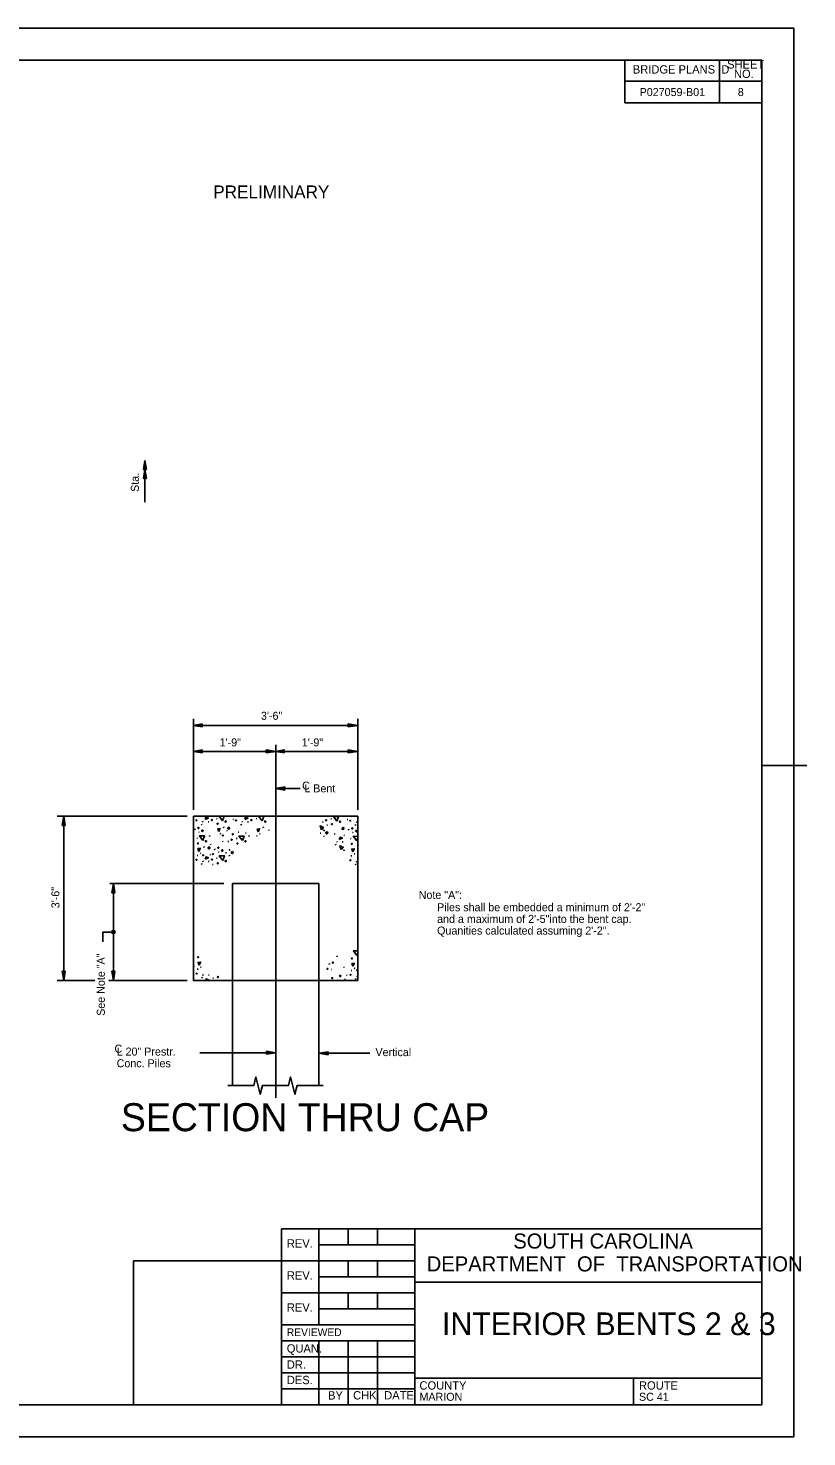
# Model space of a CAD drawing. Extents: x 437 to 537, y 571 to 720.
# Drawn here: x 503.3 to 536.8, y 570.8 to 631.3 of the extents above; entities that cross this region are included whole.
import ezdxf

# ---------------------------------------------------------------- set-up
doc = ezdxf.new("R2010")
doc.units = 0
for name, color, linetype in [('BR_AUTO DIMENSION', 7, 'Continuous'), ('BR_BORDER LINES', 7, 'Continuous'), ('BR_CENTER LINES', 7, 'Continuous'), ('BR_CONCRETE', 7, 'Continuous'), ('BR_PRESTRESSED BEAM', 7, 'Continuous'), ('BR_TABLE LINES', 7, 'Continuous'), ('BR_TEXT', 7, 'Continuous'), ('Default', 7, 'Continuous'), ('RD_SHT_IplotShp', 7, 'Continuous')]:
    doc.layers.add(name, color=color, linetype=linetype)

msp = doc.modelspace()

# ---------------------------------------------------------------- linework, layer by layer
at = {"layer": 'BR_AUTO DIMENSION'}
for p, q in [((508.265, 612.313), (508.329, 612.699)), ((508.394, 612.313), (508.265, 612.313)), ((508.265, 611.926), (508.329, 612.313)), ((508.329, 610.909), (508.329, 612.699)), ((508.329, 612.699), (508.394, 612.313)), ((508.329, 612.313), (508.394, 611.926)), ((508.394, 611.926), (508.265, 611.926)), ((517.472, 601.322), (517.059, 601.39)), ((517.059, 601.39), (517.059, 601.253)), ((517.059, 601.253), (517.472, 601.322)), ((513.943, 600.207), (513.53, 600.276)), ((513.53, 600.276), (513.53, 600.138)), ((513.53, 600.138), (513.943, 600.207)), ((517.472, 600.207), (517.059, 600.276)), ((517.059, 600.276), (517.059, 600.138)), ((517.059, 600.138), (517.472, 600.207)), ((513.943, 598.61), (514.341, 598.677)), ((514.342, 598.544), (513.943, 598.61)), ((514.341, 598.677), (514.342, 598.544)), ((504.775, 597.022), (504.842, 597.421)), ((504.842, 597.421), (504.908, 597.022)), ((504.908, 597.022), (504.775, 597.022)), ((506.906, 594.129), (506.973, 594.528)), ((507.039, 594.129), (506.906, 594.129)), ((506.973, 594.528), (507.039, 594.129)), ((506.995, 592.445), (506.52, 592.445)), ((506.52, 592.445), (506.52, 592.019)), ((504.908, 590.761), (504.775, 590.762)), ((504.775, 590.762), (504.842, 590.363)), ((504.842, 590.363), (504.908, 590.761)), ((507.039, 590.761), (506.906, 590.762)), ((506.906, 590.762), (506.973, 590.363)), ((506.973, 590.363), (507.039, 590.761)), ((513.943, 587.264), (513.544, 587.331)), ((513.544, 587.331), (513.544, 587.198)), ((513.544, 587.198), (513.943, 587.264)), ((515.8, 587.241), (516.199, 587.307)), ((516.199, 587.174), (515.8, 587.241)), ((516.199, 587.307), (516.199, 587.174))]:
    msp.add_line(p, q, dxfattribs=at)
for points in [[(510.784, 601.26), (510.784, 601.383), (510.414, 601.322)], [(510.784, 600.145), (510.784, 600.269), (510.414, 600.207)], [(514.312, 600.145), (514.312, 600.269), (513.943, 600.207)]]:
    msp.add_lwpolyline(points, close=True, dxfattribs=at)
at = {"layer": 'BR_BORDER LINES'}
for p, q in [((534.816, 629.892), (442.231, 629.895)), ((534.814, 629.892), (442.231, 629.892)), ((528.931, 628.059), (528.931, 629.893)), ((532.523, 629.892), (532.523, 629.892)), ((533.001, 628.059), (533.001, 629.892)), ((533.667, 629.892), (533.667, 629.892)), ((534.814, 572.141), (534.814, 629.892)), ((534.814, 572.141), (534.816, 629.892)), ((528.931, 628.986), (534.816, 628.986)), ((534.816, 628.059), (528.931, 628.059)), ((534.816, 626.691), (534.816, 628.059)), ((534.816, 607.306), (534.816, 626.691)), ((534.814, 599.603), (536.751, 599.603)), ((534.815, 599.604), (536.752, 599.604)), ((514.189, 572.142), (514.189, 579.705)), ((514.189, 579.705), (534.815, 579.704)), ((515.794, 579.705), (515.793, 575.58)), ((517.054, 579.017), (517.054, 579.705)), ((518.314, 579.017), (518.314, 579.705)), ((519.918, 572.142), (519.919, 579.705)), ((515.793, 579.017), (519.919, 579.017)), ((507.83, 578.33), (514.189, 578.33)), ((507.83, 572.142), (507.83, 578.33)), ((514.189, 578.33), (519.919, 578.33)), ((517.054, 577.642), (517.054, 578.33)), ((518.314, 577.642), (518.314, 578.33)), ((515.793, 577.642), (519.919, 577.642)), ((519.919, 577.413), (534.815, 577.412)), ((519.919, 577.413), (519.919, 577.413)), ((534.815, 577.412), (534.815, 577.412)), ((514.189, 576.955), (519.919, 576.954)), ((517.054, 576.267), (517.054, 576.955)), ((518.314, 576.267), (518.314, 576.955)), ((515.793, 576.267), (519.918, 576.267)), ((514.189, 575.58), (519.918, 575.579)), ((514.189, 574.892), (519.918, 574.892)), ((515.793, 574.892), (515.793, 572.142)), ((517.054, 574.892), (517.054, 572.142)), ((518.314, 574.892), (518.314, 572.142)), ((514.189, 574.205), (519.918, 574.204)), ((514.189, 573.517), (519.918, 573.517)), ((519.918, 573.288), (534.815, 573.287)), ((529.314, 572.142), (529.314, 573.287)), ((514.189, 572.83), (519.918, 572.829)), ((442.23, 572.144), (534.814, 572.141)), ((442.231, 572.141), (534.814, 572.141))]:
    msp.add_line(p, q, dxfattribs=at)
at = {"layer": 'BR_CENTER LINES'}
msp.add_line((513.943, 593.149), (513.943, 588.877), dxfattribs=at)
at = {"layer": 'BR_CONCRETE'}
for p, q in [((510.414, 597.421), (517.472, 597.421)), ((510.414, 597.421), (510.414, 590.363)), ((517.472, 597.421), (517.472, 594.44)), ((517.472, 594.44), (517.472, 590.363)), ((511.572, 590.363), (510.414, 590.363)), ((514.377, 590.363), (511.572, 590.363)), ((516.129, 590.363), (514.377, 590.363)), ((516.751, 590.363), (516.129, 590.363)), ((517.472, 590.363), (516.751, 590.363))]:
    msp.add_line(p, q, dxfattribs=at)
at = {"layer": 'BR_PRESTRESSED BEAM'}
for p, q in [((512.085, 590.363), (512.085, 594.528)), ((512.085, 594.528), (515.8, 594.528)), ((515.8, 594.528), (515.8, 590.363)), ((512.085, 590.363), (512.085, 585.851)), ((515.8, 590.363), (515.8, 585.851))]:
    msp.add_line(p, q, dxfattribs=at)
at = {"layer": 'BR_TABLE LINES'}
for points in [[(511.889, 585.851), (513.004, 585.851), (513.097, 586.223), (513.282, 585.48), (513.375, 585.851), (513.933, 585.851)], [(513.933, 585.851), (514.49, 585.851), (514.583, 586.223), (514.768, 585.48), (514.861, 585.851), (515.976, 585.851)]]:
    msp.add_lwpolyline(points, dxfattribs=at)
at = {"layer": 'Default'}
for p, q in [((510.414, 597.699), (510.414, 601.6)), ((517.472, 597.699), (517.472, 601.6)), ((510.414, 601.322), (517.472, 601.322)), ((510.414, 600.207), (513.943, 600.207)), ((513.943, 600.486), (513.943, 599.907)), ((517.472, 600.207), (513.943, 600.207)), ((513.943, 599.907), (513.943, 596.255)), ((513.943, 598.61), (514.991, 598.61)), ((510.135, 597.421), (504.563, 597.421)), ((504.842, 590.363), (504.842, 597.421)), ((510.414, 597.294), (510.43, 597.291)), ((510.818, 597.166), (510.804, 597.204)), ((511.041, 597.184), (511.076, 597.18)), ((511.401, 597.32), (511.431, 597.314)), ((511.957, 597.403), (511.95, 597.421)), ((512.098, 597.293), (512.128, 597.287)), ((512.516, 597.162), (512.502, 597.2)), ((512.739, 597.18), (512.774, 597.176)), ((513.099, 597.316), (513.129, 597.31)), ((515.949, 597.172), (515.985, 597.168)), ((516.31, 597.308), (516.339, 597.302)), ((516.865, 597.391), (516.855, 597.421)), ((517.007, 597.281), (517.037, 597.275)), ((517.171, 597.421), (517.202, 597.413)), ((517.425, 597.151), (517.411, 597.188)), ((510.483, 596.835), (510.467, 596.875)), ((510.637, 596.737), (510.664, 596.733)), ((510.771, 597.044), (510.755, 597.084)), ((511.109, 596.556), (511.096, 596.593)), ((511.551, 596.674), (511.582, 596.666)), ((511.72, 596.922), (511.704, 596.962)), ((511.86, 596.774), (511.846, 596.812)), ((512.335, 596.733), (512.362, 596.729)), ((512.469, 597.04), (512.453, 597.08)), ((512.642, 596.701), (512.676, 596.696)), ((512.808, 596.552), (512.794, 596.589)), ((513.113, 596.581), (513.144, 596.573)), ((513.249, 596.67), (513.28, 596.662)), ((513.418, 596.918), (513.403, 596.958)), ((513.655, 596.81), (513.647, 596.832)), ((513.897, 596.832), (513.899, 596.832)), ((515.853, 596.694), (515.886, 596.688)), ((516.018, 596.544), (516.005, 596.581)), ((516.137, 597.04), (516.168, 597.032)), ((516.46, 596.662), (516.491, 596.654)), ((516.867, 596.605), (516.901, 596.599)), ((517.09, 596.82), (517.074, 596.859)), ((517.244, 596.721), (517.271, 596.717)), ((517.378, 597.028), (517.362, 597.068)), ((510.554, 596.473), (510.583, 596.467)), ((510.873, 596.075), (510.857, 596.114)), ((511.159, 596.187), (511.143, 596.227)), ((511.334, 595.984), (511.318, 596.024)), ((511.669, 596.315), (511.655, 596.353)), ((511.892, 596.333), (511.927, 596.329)), ((512.252, 596.469), (512.282, 596.463)), ((513.943, 596.255), (513.943, 594.688)), ((516.53, 596.181), (516.515, 596.221)), ((516.578, 596.304), (516.564, 596.341)), ((516.8, 596.321), (516.836, 596.317)), ((517.161, 596.457), (517.191, 596.451)), ((517.472, 596.08), (517.464, 596.099)), ((510.414, 595.596), (510.434, 595.592)), ((510.568, 595.738), (510.599, 595.73)), ((510.704, 595.827), (510.735, 595.819)), ((510.774, 595.346), (510.759, 595.385)), ((510.822, 595.468), (510.808, 595.506)), ((511.044, 595.486), (511.08, 595.482)), ((511.111, 595.77), (511.145, 595.764)), ((511.231, 595.354), (511.263, 595.346)), ((511.405, 595.622), (511.434, 595.616)), ((511.488, 595.886), (511.515, 595.882)), ((511.795, 595.854), (511.828, 595.848)), ((511.961, 595.705), (511.947, 595.742)), ((517.175, 595.722), (517.206, 595.714)), ((517.311, 595.811), (517.342, 595.803)), ((517.382, 595.33), (517.366, 595.37)), ((517.429, 595.452), (517.415, 595.49)), ((511.714, 594.528), (506.816, 594.528)), ((506.973, 594.528), (506.973, 590.363)), ((513.943, 594.688), (513.943, 585.33)), ((510.414, 593.539), (510.416, 593.538)), ((510.414, 591.47), (510.42, 591.469)), ((516.251, 591.05), (516.235, 591.09)), ((516.586, 591.381), (516.572, 591.419)), ((510.414, 590.715), (510.442, 590.71)), ((510.576, 590.856), (510.607, 590.848)), ((510.711, 590.944), (510.743, 590.937)), ((510.782, 590.464), (510.767, 590.503)), ((510.83, 590.586), (510.816, 590.623)), ((511.052, 590.603), (511.088, 590.6)), ((516.319, 590.835), (516.347, 590.831)), ((516.877, 590.922), (516.864, 590.959)), ((516.981, 590.589), (517.011, 590.583)), ((517.183, 590.8), (517.214, 590.792)), ((517.319, 590.889), (517.35, 590.881)), ((517.437, 590.53), (517.423, 590.568)), ((506.176, 590.363), (504.563, 590.363)), ((510.135, 590.363), (506.784, 590.363)), ((511.239, 590.472), (511.271, 590.464)), ((511.723, 590.363), (511.716, 590.381)), ((516.927, 590.402), (516.911, 590.442)), ((517.389, 590.408), (517.374, 590.448)), ((513.943, 587.264), (510.687, 587.264)), ((517.983, 587.241), (515.8, 587.241))]:
    msp.add_line(p, q, dxfattribs=at)
for points in [[(510.52, 597.231), (510.542, 597.226), (510.556, 597.235), (510.558, 597.249), (510.554, 597.253), (510.538, 597.261), (510.524, 597.259), (510.522, 597.245), (510.52, 597.231)], [(510.916, 597.277), (510.948, 597.379), (511.052, 597.338), (510.916, 597.277)], [(511.192, 597.237), (511.2, 597.237), (511.216, 597.245), (511.222, 597.263), (511.22, 597.273), (511.204, 597.281), (511.184, 597.269), (511.18, 597.257), (511.184, 597.245), (511.192, 597.237)], [(511.663, 597.224), (511.513, 597.421), (511.736, 597.419), (511.663, 597.224)], [(511.773, 597.188), (511.783, 597.17), (511.807, 597.166), (511.817, 597.184), (511.821, 597.2), (511.811, 597.21), (511.793, 597.22), (511.775, 597.214), (511.769, 597.196), (511.773, 597.188)], [(512.219, 597.227), (512.24, 597.222), (512.254, 597.231), (512.256, 597.245), (512.252, 597.249), (512.236, 597.257), (512.223, 597.255), (512.22, 597.241), (512.219, 597.227)], [(512.523, 597.421), (512.526, 597.421), (512.527, 597.421)], [(512.615, 597.273), (512.646, 597.375), (512.75, 597.334), (512.615, 597.273)], [(512.89, 597.233), (512.898, 597.233), (512.914, 597.241), (512.92, 597.259), (512.918, 597.269), (512.902, 597.277), (512.882, 597.265), (512.878, 597.253), (512.882, 597.241), (512.89, 597.233)], [(513.361, 597.22), (513.212, 597.417), (513.434, 597.415), (513.361, 597.22)], [(513.471, 597.184), (513.481, 597.166), (513.505, 597.162), (513.515, 597.18), (513.519, 597.196), (513.509, 597.206), (513.491, 597.216), (513.474, 597.21), (513.468, 597.192), (513.471, 597.184)], [(516.101, 597.226), (516.109, 597.226), (516.125, 597.233), (516.131, 597.251), (516.129, 597.261), (516.113, 597.269), (516.093, 597.257), (516.089, 597.245), (516.093, 597.233), (516.101, 597.226)], [(516.572, 597.212), (516.422, 597.409), (516.645, 597.407), (516.572, 597.212)], [(516.682, 597.176), (516.692, 597.159), (516.716, 597.155), (516.726, 597.172), (516.73, 597.188), (516.72, 597.198), (516.702, 597.208), (516.684, 597.202), (516.678, 597.184), (516.682, 597.176)], [(517.127, 597.216), (517.149, 597.21), (517.163, 597.22), (517.165, 597.233), (517.161, 597.237), (517.145, 597.245), (517.131, 597.243), (517.13, 597.23), (517.127, 597.216)], [(517.411, 597.421), (517.421, 597.411)], [(517.421, 597.411), (517.435, 597.409), (517.449, 597.415), (517.451, 597.421)], [(510.414, 596.639), (510.416, 596.642), (510.414, 596.653)], [(510.605, 596.91), (510.615, 596.893), (510.637, 596.895), (510.646, 596.908), (510.648, 596.93), (510.635, 596.936), (510.625, 596.938), (510.613, 596.934), (510.609, 596.93), (510.605, 596.91)], [(510.816, 596.376), (510.666, 596.573), (510.889, 596.572), (510.816, 596.376)], [(510.767, 596.8), (510.778, 596.776), (510.798, 596.765), (510.814, 596.776), (510.822, 596.788), (510.822, 596.812), (510.804, 596.83), (510.782, 596.828), (510.773, 596.818), (510.767, 596.8)], [(511.436, 597.08), (511.46, 597.08), (511.472, 597.092), (511.466, 597.113), (511.44, 597.115), (511.436, 597.103), (511.431, 597.093), (511.436, 597.08), (511.432, 597.084)], [(511.49, 596.759), (511.452, 596.875), (511.557, 596.889), (511.49, 596.759)], [(511.665, 596.575), (511.679, 596.573), (511.693, 596.579), (511.697, 596.591), (511.691, 596.601), (511.679, 596.609), (511.665, 596.615), (511.657, 596.599), (511.653, 596.587), (511.665, 596.575)], [(511.892, 596.881), (511.917, 596.867), (511.951, 596.881), (511.964, 596.922), (511.945, 596.942), (511.919, 596.948), (511.907, 596.94), (511.893, 596.918), (511.884, 596.9), (511.892, 596.881)], [(512.083, 596.631), (512.094, 596.619), (512.106, 596.627), (512.114, 596.638), (512.11, 596.658), (512.1, 596.66), (512.087, 596.658), (512.075, 596.646), (512.083, 596.631)], [(512.514, 596.372), (512.364, 596.57), (512.587, 596.568), (512.514, 596.372)], [(513.188, 596.755), (513.15, 596.871), (513.255, 596.885), (513.188, 596.755)], [(515.906, 596.838), (515.853, 597.001), (515.993, 596.94), (515.906, 596.838)], [(516.016, 596.798), (516.038, 596.808), (516.03, 596.816), (516.016, 596.822), (516.01, 596.808), (516.016, 596.798)], [(516.095, 596.704), (516.121, 596.662), (516.146, 596.664), (516.156, 596.674), (516.178, 596.696), (516.164, 596.729), (516.137, 596.745), (516.117, 596.737), (516.101, 596.721), (516.095, 596.704)], [(516.345, 597.068), (516.369, 597.068), (516.381, 597.08), (516.375, 597.101), (516.349, 597.103), (516.345, 597.092), (516.339, 597.082), (516.345, 597.068), (516.341, 597.072)], [(516.8, 596.869), (516.826, 596.855), (516.86, 596.869), (516.873, 596.91), (516.854, 596.93), (516.828, 596.936), (516.816, 596.928), (516.802, 596.906), (516.793, 596.889), (516.8, 596.869)], [(517.212, 596.895), (517.222, 596.877), (517.244, 596.879), (517.254, 596.893), (517.256, 596.914), (517.242, 596.92), (517.232, 596.922), (517.22, 596.918), (517.216, 596.914), (517.212, 596.895)], [(517.423, 596.361), (517.273, 596.558), (517.472, 596.556)], [(517.374, 596.784), (517.385, 596.761), (517.405, 596.749), (517.421, 596.761), (517.429, 596.772), (517.429, 596.796), (517.411, 596.814), (517.389, 596.812), (517.38, 596.802), (517.374, 596.784)], [(510.589, 596.233), (510.613, 596.233), (510.625, 596.244), (510.619, 596.266), (510.593, 596.268), (510.589, 596.256), (510.583, 596.246), (510.589, 596.233), (510.585, 596.237)], [(510.642, 595.911), (510.605, 596.028), (510.71, 596.042), (510.642, 595.911)], [(510.926, 596.341), (510.936, 596.323), (510.96, 596.319), (510.969, 596.337), (510.973, 596.353), (510.964, 596.363), (510.946, 596.372), (510.928, 596.367), (510.922, 596.349), (510.926, 596.341)], [(511.044, 596.034), (511.07, 596.02), (511.103, 596.034), (511.117, 596.075), (511.098, 596.095), (511.072, 596.101), (511.06, 596.093), (511.046, 596.071), (511.037, 596.053), (511.044, 596.034)], [(511.456, 596.059), (511.466, 596.042), (511.488, 596.043), (511.497, 596.057), (511.499, 596.079), (511.486, 596.085), (511.476, 596.087), (511.464, 596.083), (511.46, 596.079), (511.456, 596.059)], [(511.618, 595.949), (511.63, 595.925), (511.649, 595.914), (511.665, 595.925), (511.673, 595.937), (511.673, 595.961), (511.655, 595.979), (511.633, 595.976), (511.624, 595.967), (511.618, 595.949)], [(511.959, 595.959), (511.98, 595.969), (511.972, 595.976), (511.959, 595.982), (511.953, 595.969), (511.959, 595.959)], [(512.043, 596.386), (512.051, 596.386), (512.067, 596.394), (512.073, 596.412), (512.071, 596.422), (512.055, 596.43), (512.035, 596.418), (512.031, 596.406), (512.035, 596.394), (512.043, 596.386)], [(512.288, 596.229), (512.311, 596.229), (512.323, 596.241), (512.317, 596.262), (512.292, 596.264), (512.288, 596.252), (512.282, 596.242), (512.288, 596.229), (512.284, 596.233)], [(512.624, 596.337), (512.634, 596.319), (512.658, 596.315), (512.668, 596.333), (512.672, 596.349), (512.662, 596.359), (512.644, 596.369), (512.626, 596.363), (512.62, 596.345), (512.624, 596.337)], [(516.676, 596.414), (516.708, 596.516), (516.812, 596.475), (516.676, 596.414)], [(516.757, 595.986), (516.704, 596.15), (516.844, 596.089), (516.757, 595.986)], [(516.867, 595.947), (516.889, 595.957), (516.881, 595.965), (516.867, 595.971), (516.862, 595.957), (516.867, 595.947)], [(517.196, 596.217), (517.22, 596.217), (517.232, 596.229), (517.226, 596.25), (517.2, 596.252), (517.196, 596.241), (517.191, 596.231), (517.196, 596.217), (517.192, 596.221)], [(517.25, 595.896), (517.212, 596.012), (517.317, 596.026), (517.25, 595.896)], [(517.472, 596.492), (517.423, 596.361)], [(510.414, 595.852), (510.422, 595.86), (510.414, 595.88)], [(510.524, 595.533), (510.546, 595.527), (510.56, 595.537), (510.562, 595.551), (510.558, 595.555), (510.542, 595.563), (510.528, 595.561), (510.526, 595.547), (510.524, 595.533)], [(510.818, 595.728), (510.832, 595.726), (510.845, 595.732), (510.849, 595.744), (510.843, 595.754), (510.832, 595.762), (510.818, 595.768), (510.81, 595.752), (510.806, 595.74), (510.818, 595.728)], [(510.92, 595.579), (510.952, 595.681), (511.056, 595.64), (510.92, 595.579)], [(511.196, 595.539), (511.204, 595.539), (511.22, 595.547), (511.226, 595.565), (511.224, 595.575), (511.208, 595.583), (511.188, 595.571), (511.184, 595.559), (511.188, 595.547), (511.196, 595.539)], [(511.235, 595.783), (511.247, 595.772), (511.259, 595.78), (511.267, 595.791), (511.263, 595.811), (511.253, 595.813), (511.239, 595.811), (511.228, 595.799), (511.235, 595.783)], [(511.44, 595.382), (511.464, 595.382), (511.476, 595.393), (511.47, 595.415), (511.444, 595.417), (511.44, 595.405), (511.434, 595.395), (511.44, 595.382), (511.436, 595.385)], [(511.667, 595.525), (511.517, 595.722), (511.74, 595.72), (511.667, 595.525)], [(511.777, 595.49), (511.787, 595.472), (511.811, 595.468), (511.821, 595.486), (511.825, 595.502), (511.815, 595.512), (511.797, 595.521), (511.779, 595.515), (511.773, 595.498), (511.777, 595.49)], [(512.037, 595.864), (512.063, 595.823), (512.089, 595.825), (512.098, 595.835), (512.12, 595.856), (512.106, 595.89), (512.079, 595.906), (512.059, 595.898), (512.043, 595.882), (512.037, 595.864)], [(517.131, 595.518), (517.153, 595.512), (517.167, 595.521), (517.169, 595.535), (517.165, 595.539), (517.149, 595.547), (517.135, 595.545), (517.133, 595.531), (517.131, 595.518)], [(510.597, 591.35), (510.621, 591.35), (510.633, 591.362), (510.627, 591.384), (510.601, 591.386), (510.597, 591.374), (510.591, 591.364), (510.597, 591.35), (510.593, 591.354)], [(510.65, 591.029), (510.613, 591.145), (510.717, 591.159), (510.65, 591.029)], [(516.373, 591.125), (516.383, 591.108), (516.404, 591.109), (516.414, 591.123), (516.416, 591.145), (516.402, 591.151), (516.393, 591.153), (516.381, 591.149), (516.377, 591.145), (516.373, 591.125)], [(517.204, 591.295), (517.228, 591.295), (517.24, 591.306), (517.234, 591.328), (517.208, 591.33), (517.204, 591.318), (517.198, 591.308), (517.204, 591.295), (517.2, 591.299)], [(517.258, 590.974), (517.22, 591.09), (517.324, 591.104), (517.258, 590.974)], [(517.431, 591.439), (517.281, 591.635), (517.472, 591.634)], [(517.472, 591.549), (517.431, 591.439)], [(510.414, 590.962), (510.43, 590.978), (510.416, 591.011), (510.414, 591.013)], [(510.532, 590.651), (510.554, 590.645), (510.568, 590.655), (510.57, 590.669), (510.566, 590.672), (510.55, 590.68), (510.536, 590.678), (510.534, 590.665), (510.532, 590.651)], [(511.448, 590.499), (511.472, 590.499), (511.484, 590.511), (511.478, 590.533), (511.452, 590.535), (511.448, 590.523), (511.442, 590.513), (511.448, 590.499), (511.444, 590.503)], [(516.152, 590.85), (516.164, 590.838), (516.176, 590.846), (516.184, 590.857), (516.18, 590.877), (516.17, 590.879), (516.156, 590.877), (516.144, 590.865), (516.152, 590.85)], [(516.357, 590.448), (516.381, 590.448), (516.393, 590.459), (516.387, 590.481), (516.361, 590.483), (516.357, 590.471), (516.351, 590.461), (516.357, 590.448), (516.353, 590.451)], [(516.694, 590.556), (516.704, 590.538), (516.728, 590.534), (516.737, 590.552), (516.741, 590.568), (516.731, 590.578), (516.714, 590.587), (516.696, 590.582), (516.69, 590.564), (516.694, 590.556)], [(517.139, 590.595), (517.161, 590.589), (517.175, 590.599), (517.177, 590.613), (517.173, 590.617), (517.157, 590.625), (517.143, 590.623), (517.141, 590.609), (517.139, 590.595)], [(517.433, 590.79), (517.447, 590.788), (517.46, 590.794), (517.464, 590.806), (517.458, 590.816), (517.447, 590.824), (517.433, 590.83), (517.425, 590.814), (517.421, 590.802), (517.433, 590.79)], [(510.978, 590.363), (510.956, 590.432), (511.096, 590.371), (511.089, 590.363)]]:
    msp.add_lwpolyline(points, dxfattribs=at)
for radius in [0.0741, 0.0486, 0.022]:
    msp.add_circle((506.973, 592.445), radius, dxfattribs=at)
at = {"layer": 'RD_SHT_IplotShp'}
msp.add_lwpolyline([(437.19, 631.267), (536.19, 631.267), (536.19, 570.767), (437.19, 570.767)], close=True, dxfattribs=at)

# ---------------------------------------------------------------- texts
at = {"layer": 'BR_AUTO DIMENSION'}
msp.add_text('Sta.', height=0.3438, rotation=90, dxfattribs=at).set_placement((508.067, 611.352))
at = {"layer": 'BR_TEXT'}
for s, height, rotation, p in [('SHEET', 0.3575, 359.99821, (533.328, 629.533)), ('BRIDGE PLANS ID', 0.3575, 359.99821, (529.279, 629.317)), ('NO.', 0.3575, 359.99821, (533.624, 629.127)), ('P027059-B01', 0.34375, 359.99821, (529.572, 628.35)), ('8', 0.344, 359.99821, (533.789, 628.35)), ('3\'-6"', 0.3438, 90, (504.656, 593.468)), ('See Note "A"', 0.34375, 90, (506.606, 588.847)), ('REV.', 0.3575, 359.99821, (514.422, 578.895)), ('SOUTH CAROLINA', 0.6486, 359.99821, (524.146, 578.853)), ('DEPARTMENT  OF  TRANSPORTATION', 0.6486, 359.99821, (520.427, 577.87)), ('REV.', 0.3575, 359.99821, (514.422, 577.52)), ('REV.', 0.3575, 359.99821, (514.422, 576.145)), ('INTERIOR BENTS 2 & 3', 0.97396, 360, (521.085, 575.135)), ('REVIEWED', 0.33, 359.99821, (514.42, 575.094)), ('QUAN.', 0.3575, 359.99821, (514.419, 574.384)), ('DR.', 0.3575, 359.99821, (514.419, 573.692)), ('DES.', 0.3575, 359.99821, (514.422, 573.029)), ('COUNTY', 0.3575, 359.99821, (520.118, 572.795)), ('ROUTE', 0.3575, 359.99821, (529.545, 572.795)), ('BY', 0.3575, 359.99821, (516.193, 572.367)), ('CHK.', 0.3575, 359.99821, (517.268, 572.371)), ('DATE', 0.3575, 359.99821, (518.602, 572.371)), ('MARION', 0.3438, 359.99821, (520.118, 572.315)), ('SC 41', 0.3438, 359.99821, (529.545, 572.315))]:
    msp.add_text(s, height=height, rotation=rotation, dxfattribs=at).set_placement(p)
for s, height, p in [('3\'-6"', 0.3438, (513.312, 601.562)), ('1\'-9"', 0.3438, (511.535, 600.419)), ('1\'-9"', 0.3438, (515.064, 600.419)), ('C', 0.344, (515.08, 598.563)), ('L Bent', 0.3438, (515.174, 598.445)), ('Note "A":', 0.3438, (520.084, 593.871)), ('Piles shall be embedded a minimum of 2\'-2" ', 0.34375, (520.875, 593.34)), ('and a maximum of 2\'-5"into the bent cap. ', 0.34375, (520.875, 592.838)), ('Quanities calculated assuming 2\'-2".', 0.34375, (520.875, 592.337)), ('C', 0.344, (507.02, 587.264)), ('L 20" Prestr. ', 0.34375, (507.114, 587.141)), ('Vertical', 0.3438, (518.228, 587.117)), ('Conc. Piles', 0.34375, (507.114, 586.639)), ('SECTION THRU CAP', 1.20273, (507.296, 583.893))]:
    msp.add_text(s, height=height, dxfattribs=at).set_placement(p)
at = {"layer": 'Default'}
msp.add_text('PRELIMINARY', height=0.55, dxfattribs=at).set_placement((511.262, 623.961))

doc.saveas('drawing.dxf')
